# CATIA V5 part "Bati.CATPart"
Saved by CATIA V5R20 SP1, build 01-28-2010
Part number: Bati
Bounding box of the stored display mesh (mm): x -10 to 10, y -40 to 40, z 0 to 64.205
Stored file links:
  E:\EDELI\gcausse\Edeli_2012_681_gcausse\Bati.CATPart
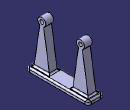
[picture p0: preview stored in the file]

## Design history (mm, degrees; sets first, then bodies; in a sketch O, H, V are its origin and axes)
Body1 (main body)
  Sketch1 on xy-plane, origin (0, 0, 0), H (1, 0, 0), V (0, 1, 0)
    line L1 (-10, -40) -> (10, -40)
    line L2 (10, -40) -> (10, 40)
    line L3 (10, 40) -> (-10, 40)
    line L4 (-10, 40) -> (-10, -40)
    horizontal: L1 H, L3 H
    vertical: L2 V, L4 V
  Pad1: profile Sketch1, direction (0, 0, 1), length 5
  Sketch2 on end face of Pad1, origin (0, 0, 5), H (1, 0, 0), V (0, 1, 0)
    line L1 (-5, 35) -> (5, 35)
    line L2 (5, 35) -> (5, 15)
    line L3 (5, 15) -> (-5, 15)
    line L4 (-5, 15) -> (-5, 35)
    line L5 (-5, -35) -> (5, -35)
    line L6 (5, -35) -> (5, -15)
    line L7 (5, -15) -> (-5, -15)
    line L8 (-5, -15) -> (-5, -35)
    reference projected line E1 (-10, 40) -> (-10, -40) from edge [face of Pad1 from Sketch1.L4 | end face of Pad1]
    reference projected line E2 (-10, 40) -> (-10, -40) from edge [face of Pad1 from Sketch1.L4 | end face of Pad1]
    reference projected line E3 (-10, -40) -> (10, -40) from edge [face of Pad1 from Sketch1.L1 | end face of Pad1]
    reference projected line E4 (-10, -40) -> (10, -40) from edge [face of Pad1 from Sketch1.L1 | end face of Pad1]
    reference projected line E5 (-10, -40) -> (10, -40) from edge [face of Pad1 from Sketch1.L1 | end face of Pad1]
    reference projected line E6 (-10, -40) -> (10, -40) from edge [face of Pad1 from Sketch1.L1 | end face of Pad1]
    distance L4 E1 = 5
    distance L8 E2 = 5
    distance L5 E3 = 5
    distance L7 E4 = 25
    distance L3 E5 = 55
    distance L1 E6 = 75
    distance L4 L2 = 10
    horizontal: L1 H, L3 H, L5 H, L7 H
    vertical: L2 V, L4 V, L6 V, L8 V
  Pad2: profile Sketch2, direction (0, 0, 1), length 60
  Sketch3 on face of Pad2 from Sketch2.L6, origin (5, 0, 0), H (0, 1, 0), V (0, 0, 1)
    line L1 (-35, 5) -> (-27.5, 54.4343)
    point P1 (-35, 5)
    point P2 (-27.5, 54.4343)
    line L2 (-22.5, 54.4343) -> (-15, 5)
    point P3 (-22.5, 54.4343)
    point P4 (-15, 5)
    arc A1 centre (-25, 59) radius 5.2053 from (-22.5, 54.4343) to (-27.5, 54.4343) ccw
    point P5 (-25, 59)
    point P6 (-55, 40)
    reference projected point E1 (-15, 5) from vertex [face of Pad2 from Sketch2.L7 | end face of Pad1 | face of Pad2 from Sketch2.L6]
    reference projected point E2 (-35, 5) from vertex [face of Pad2 from Sketch2.L6 | end face of Pad1 | face of Pad2 from Sketch2.L5]
    reference projected line E3 (-15, 5) -> (-15, 40) from edge [face of Pad2 from Sketch2.L7 | face of Pad2 from Sketch2.L6]
    reference projected line E4 (-35, 5) -> (-35, 40) from edge [face of Pad2 from Sketch2.L6 | face of Pad2 from Sketch2.L5]
    reference projected line E5 (-35, 65) -> (-15, 65) from edge [face of Pad2 from Sketch2.L6 | end face of Pad2]
    line L3 (-15, 5) -> (-15, 80)
    line L4 (-15, 80) -> (-35, 80)
    line L5 (-35, 80) -> (-35, 5)
    distance P5 E5 = 6
    length L2 = 50
    length L1 = 50
    distance P2 P3 = 5
    coincidence: P4 E1, P1 E2
    equidistance: E3 E4 P5
    vertical: L3 V, L5 V
    horizontal: L4 H
  Pocket1: profile Sketch3, direction (-1, 0, 0), length 35
  Sketch4 on face of Pad2 from Sketch2.L6, origin (5, -25.3906, 32.2803), H (0, 1, 0), V (0, 0, 1)
    point P1 (0.3906, 26.7197)
    reference projected arc E2 centre (0.3906, 26.7197) radius 5.2053 from (3.0464, 22.2428) to (-2.2652, 22.2428) ccw from edge [face of Pad2 from Sketch2.L6 | face of Pocket1 from Sketch3.A1]
    concentricity: P1 E2
  Hole1: placed by Sketch4, at (5, -25, 59) direction (-1, 0, 0), diameter 5, depth 10
  Sketch5 on face of Pad2 from Sketch2.L2, origin (5, 0, 0), H (0, 1, 0), V (0, 0, 1)
    line L1 (15, 5) -> (22.5, 54.4343)
    point P1 (15, 5)
    point P2 (22.5, 54.4343)
    arc A1 centre (25, 59) radius 5.2053 from (22.5, 54.4343) to (27.5, 54.4343) cw
    point P3 (25, 59)
    point P4 (27.5, 54.4343)
    line L2 (27.5, 54.4343) -> (35, 5)
    point P5 (35, 5)
    reference projected point E1 (15, 5) from vertex [face of Pad2 from Sketch2.L2 | end face of Pad1 | face of Pad2 from Sketch2.L3]
    reference projected point E2 (35, 5) from vertex [face of Pad2 from Sketch2.L2 | end face of Pad1 | face of Pad2 from Sketch2.L1]
    reference projected line E3 (15, 65) -> (35, 65) from edge [face of Pad2 from Sketch2.L2 | end face of Pad2]
    reference projected line E4 (35, 5) -> (35, 40) from edge [face of Pad2 from Sketch2.L1 | face of Pad2 from Sketch2.L2]
    reference projected line E5 (15, 5) -> (15, 40) from edge [face of Pad2 from Sketch2.L2 | face of Pad2 from Sketch2.L3]
    line L3 (35, 5) -> (35, 70)
    line L4 (35, 70) -> (15, 70)
    line L5 (15, 70) -> (15, 5)
    distance P3 E3 = 6
    length L2 = 50
    length L1 = 50
    distance P4 P2 = 5
    coincidence: P1 E1, P5 E2
    equidistance: E4 E5 P3
    vertical: L3 V, L5 V
    horizontal: L4 H
  Pocket2: profile Sketch5, direction (-1, 0, 0), length 35
  Sketch6 on face of Pad2 from Sketch2.L2, origin (5, 26.0729, 32.6317), H (0, 1, 0), V (0, 0, 1)
    point P1 (-1.0729, 26.3683)
    reference projected arc E1 centre (-1.0729, 26.3683) radius 5.2053 from (3.3238, 23.5818) to (-5.4696, 23.5818) ccw from edge [face of Pocket2 from Sketch5.A1 | face of Pad2 from Sketch2.L2]
    concentricity: P1 E1
  Hole2: placed by Sketch6, at (5, 25, 59) direction (-1, 0, 0), diameter 5, depth 10
  Fillet1: radius 2, on end face of Pad1
  Fillet2: radius 4, on edge [face of Pad1 from Sketch1.L4 | face of Pad1 from Sketch1.L3]; edge [face of Pad1 from Sketch1.L3 | face of Pad1 from Sketch1.L2]; edge [face of Pad1 from Sketch1.L1 | face of Pad1 from Sketch1.L4]; edge [face of Pad1 from Sketch1.L2 | face of Pad1 from Sketch1.L1]
  Fillet3: radius 1, on edge [face of Pocket2 from Sketch5.L2 | face of Pocket2 from Sketch5.A1]; edge [face of Pocket2 from Sketch5.A1 | face of Pocket2 from Sketch5.L1]; edge [face of Pocket1 from Sketch3.L2 | face of Pocket1 from Sketch3.A1]; edge [face of Pocket1 from Sketch3.A1 | face of Pocket1 from Sketch3.L1]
